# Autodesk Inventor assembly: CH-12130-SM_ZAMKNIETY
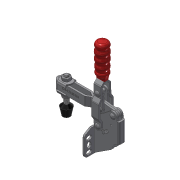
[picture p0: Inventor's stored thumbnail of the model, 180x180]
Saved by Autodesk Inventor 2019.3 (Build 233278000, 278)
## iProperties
Company: Î¢ÈíÖÐ¹ú
Created: 2012-09
Part Number: CH-12130-SM_ZAMKNIETY
Material: Ogólny
Description: STEP AP203
Document SubType Name: Assembly
Designer: CADENGINEERING4
Sending System: SolidWorks 2010
Preprocessor: SwSTEP 2.0
Title: CH-12130-SM.STEP
Author: Î¢ÈíÓÃ»§
Revision Number: ÈÎºÎ
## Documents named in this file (12)
- D:\Vault_2016\Projekty\NASZ KATALOG\CLAMPTEK\STRONA\Vertical toggle clamp\CH-12130-SM\CH-12130-SM_ZAMKNIETY.iam
- D:\Vault_2016\Projekty\NASZ KATALOG\CLAMPTEK\STEP FILES\Vertical toggle clamp\CH-12130-SM\CH-12130-04 CONNECTING-PLATE.ipt
- D:\Vault_2016\Projekty\NASZ KATALOG\CLAMPTEK\STEP FILES\Vertical toggle clamp\CH-12130-SM\CH-12130-SM-01 SIDE MOUNTED.ipt
- D:\Vault_2016\Projekty\NASZ KATALOG\CLAMPTEK\STEP FILES\Vertical toggle clamp\CH-12130-SM\CH-12130-08.ipt
- D:\Vault_2016\Projekty\NASZ KATALOG\CLAMPTEK\STEP FILES\Vertical toggle clamp\CH-12130-SM\CH-FW-516.ipt
- D:\Vault_2016\Projekty\NASZ KATALOG\CLAMPTEK\STEP FILES\Vertical toggle clamp\CH-12130-SM\CH-FC-56212 Nut.ipt
- D:\Vault_2016\Projekty\NASZ KATALOG\CLAMPTEK\STEP FILES\Vertical toggle clamp\CH-12130-SM\CH-12130-03 STRAIGHT HANDLE.ipt
- D:\Vault_2016\Projekty\NASZ KATALOG\CLAMPTEK\STEP FILES\Vertical toggle clamp\CH-12130-SM\CH-12130-05.ipt
- D:\Vault_2016\Projekty\NASZ KATALOG\CLAMPTEK\STEP FILES\Vertical toggle clamp\CH-12130-SM\CH-12130-07.ipt
- D:\Vault_2016\Projekty\NASZ KATALOG\CLAMPTEK\STEP FILES\Vertical toggle clamp\CH-12130-SM\CH-FC-56212 SPINDLE SUPPLIED.ipt
- D:\Vault_2016\Projekty\NASZ KATALOG\CLAMPTEK\STEP FILES\Vertical toggle clamp\CH-12130-SM\CH-12130-06.ipt
- D:\Vault_2016\Projekty\NASZ KATALOG\CLAMPTEK\STEP FILES\Vertical toggle clamp\CH-12130-SM\CH-12130-SM-02 U-BAR.ipt
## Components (15 placed, 15 different names)
1. CH-12130-04 CONNECTING-PLATE_1
2. CH-12130-SM-01 SIDE MOUNTED_2
3. CH-12130-08_3
4. CH-FW-516_4
5. CH-FC-56212 Nut_5
6. CH-12130-03 STRAIGHT HANDLE_6
7. CH-FC-56212 Nut_7
8. CH-12130-05_8
9. CH-12130-08_9
10. CH-12130-07_10
11. CH-FC-56212 SPINDLE SUPPLIED_11
12. CH-12130-06_12
13. CH-12130-06_13
14. CH-12130-SM-02 U-BAR_14
15. CH-FW-516_15
